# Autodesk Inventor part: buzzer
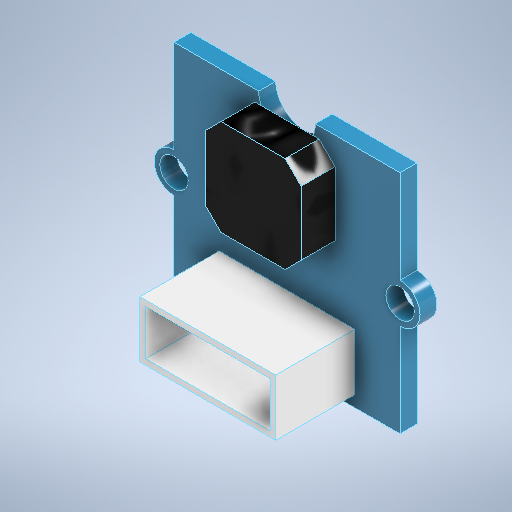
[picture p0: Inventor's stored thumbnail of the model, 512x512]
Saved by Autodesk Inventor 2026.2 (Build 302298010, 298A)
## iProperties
Created: 2026-09
Part Number: buzzer
Material: Générique
Document SubType Name: Modeling
Designer: mel
Density: 1 g/cm^3
Appearance: Bleu ciel foncé
Author: mel
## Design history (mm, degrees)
sketch "Esquisse1"
  geometry: L1 (-10, -10)-(-10, -1.75); L2 (-10, 1.75)-(-10, 10); L3 (10, 10)-(10, 1.769); L4 (10, -1.769)-(10, -10); L5 (-10, 10)-(-2.5, 10); L6 (2.5, 10)-(10, 10); L7 (10, -10)-(2.5, -10); L8 (-2.5, -10)-(-10, -10); C1 r 1.25 at (-10, 0); C2 r 1.25 at (10, 0); A1 r 1.75 centre (-10, 0) between (-10, 1.75) and (-10, -1.75); A2 r 1.769 centre (10, 0) between (10, -1.769) and (10, 1.769); A3 r 2.5 centre (0, 10) between (-2.5, 10) and (2.5, 10); A4 r 2.5 centre (0, -10) between (2.5, -10) and (-2.5, -10); 1 further point
  constraints: 16 end point, 8 parallel, 8 point on circle, 6 centre point, 4 perpendicular, 2 coincident, 2 horizontal, 1 point on line
  dimensions: "d4" = 3.5 diameter of A1; "d5" = 2.5 diameter of C1; "d6" = 5 diameter of A3; "d7" = 5 diameter of A4
extrude "Extrusion1" new body sketch "Esquisse1" distance "d8" = 1.5; taper "d9" = 0 deg
sketch "Esquisse4"
  geometry: L1 (-6, -4)-(6, -4); L2 (6, -4)-(6, -9); L3 (6, -9)-(-6, -9); L4 (-6, -9)-(-6, -4); L5 (-10, -1.75)-(-10, -10) reference; L6 (10, -10)-(10, -1.769) reference; L7 (-10, -10)-(-2.5, -10) reference; 1 further point
  constraints: 8 end point, 2 parallel, 1 horizontal, 1 perpendicular
  dimensions: "d19" = 4 distance between parallel lines of L4 L5; "d20" = 4 distance between parallel lines of L6 L2 (= d19); "d21" = 5 distance between parallel lines of L1 L3; "d22" = 1 distance between parallel lines of L7 L3; "d25" = 12 distance between parallel lines of L4 L2 (derived)
extrude "Extrusion3" join sketch "Esquisse4" distance "d23" = 7; taper "d24" = 0 deg
sketch "Esquisse5"
  geometry: L1 (4.25, 9)-(-4.25, 9); L2 (-4.25, 9)-(-4.25, 0.5); L3 (-4.25, 0.5)-(4.25, 0.5); L4 (4.25, 0.5)-(4.25, 9); L5 (10, 10)-(2.5, 10) reference; L6 (10, 1.769)-(10, 10) reference; L7 (-10, 10)-(-10, 1.75) reference; 1 further point
  constraints: 8 end point, 2 parallel, 1 horizontal, 1 perpendicular
  dimensions: "d26" = 1 distance between parallel lines of L1 L5; "d27" = 8.5 distance between parallel lines of L3 L1; "d28" = 8.5 distance between parallel lines of L2 L4 (= d27); "d29" = 5.75 distance between parallel lines of L4 L6; "d30" = 5.75 distance between parallel lines of L7 L2 (derived)
extrude "Extrusion4" join sketch "Esquisse5" distance "d31" = 3; taper "d32" = 0 deg
chamfer "Chanfrein1" distance "d33" = 1.414; stored, may be unused: second distance "d34" = 2, angle "d35" = 45 deg
sketch "Esquisse6"
  geometry: L1 (-6, -9)-(6, -9) reference; L2 (6, -9)-(6, -4) reference; L3 (6, -4)-(-6, -4) reference; L4 (-6, -4)-(-6, -9) reference; L5 (5.5, -4.5)-(5.5, -8.5); L6 (5.5, -8.5)-(-5.5, -8.5); L7 (-5.5, -8.5)-(-5.5, -4.5); L8 (-5.5, -4.5)-(5.5, -4.5); 1 further point
  constraints: 8 end point, 3 other
  dimensions: "d36" = 0.5 distance between parallel lines of L2 L5
extrude "Extrusion5" cut sketch "Esquisse6" distance "d37" = 5; taper "d38" = 0 deg
node "Solide1"
node "Boucle projetée1"
